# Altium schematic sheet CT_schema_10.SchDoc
size 254 x 194 mm
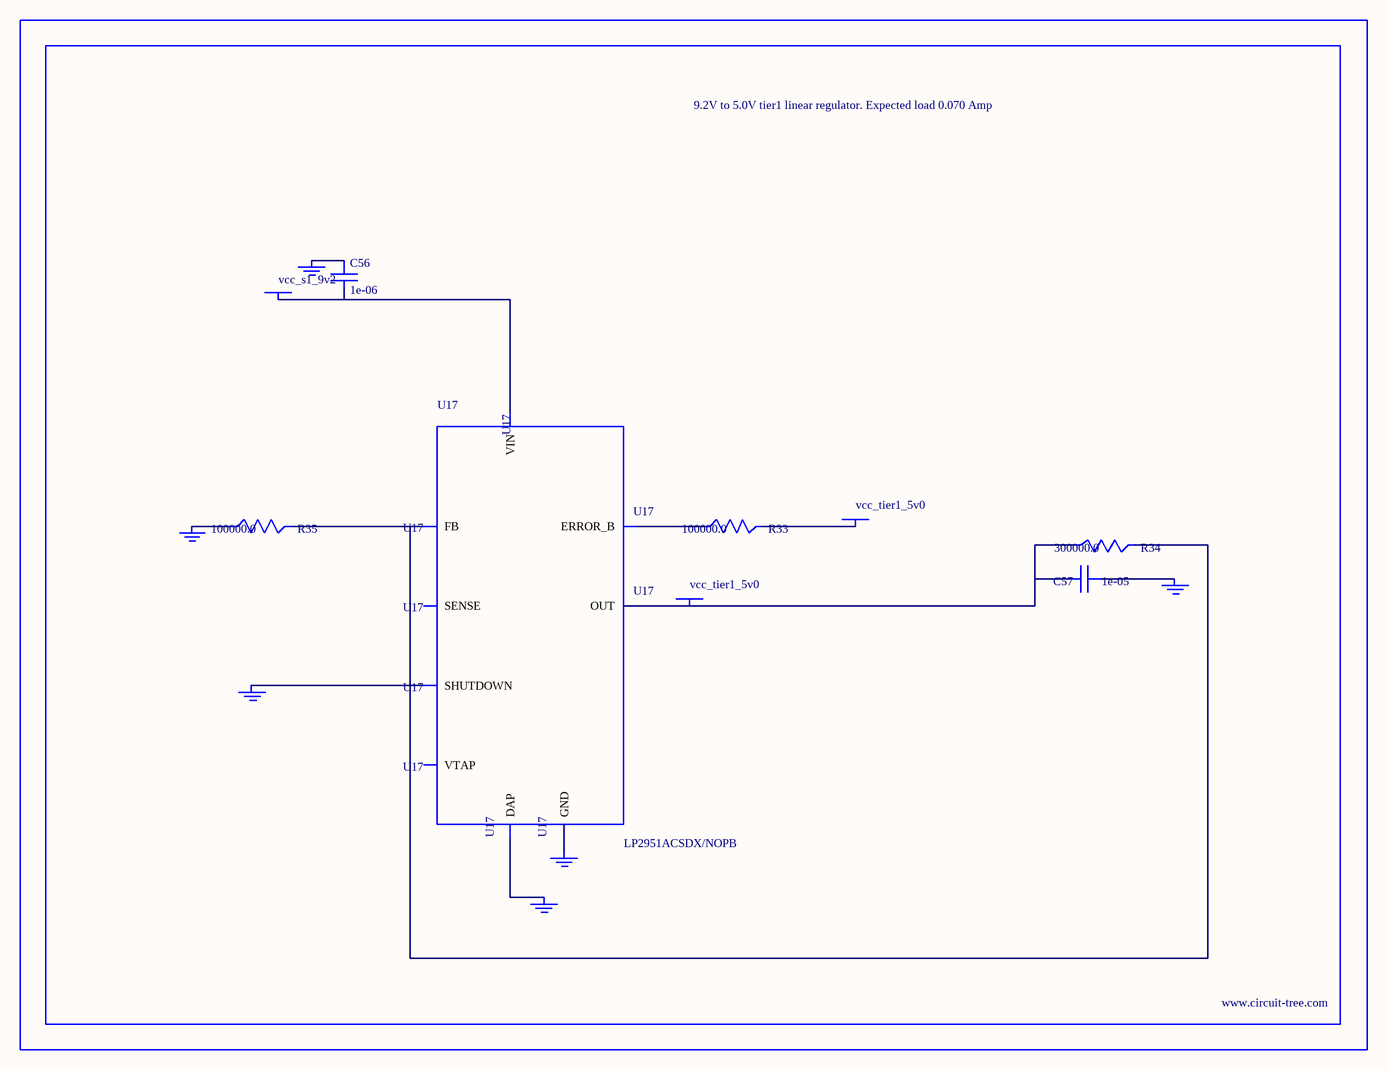
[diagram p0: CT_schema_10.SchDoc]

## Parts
BORDER9  (no value)
C56  1e-06  [C0603]
C57  1e-05  [C1210]
GND_INSTANCE_9_0  (no value)
GND_INSTANCE_9_1  (no value)
GND_INSTANCE_9_2  (no value)
GND_INSTANCE_9_3  (no value)
GND_INSTANCE_9_4  (no value)
GND_INSTANCE_9_5  (no value)
POWER_INSTANCE_9_0  vcc_tier1_5v0
POWER_INSTANCE_9_1  vcc_s1_9v2
POWER_INSTANCE_9_2  vcc_tier1_5v0
R33  100000.0  [R0603]
R34  300000.0  [R0603]
R35  100000.0  [R0603]
U17  LP2951ACSDX/NOPB  [WSON-8]

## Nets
NetC56_1: C56.1 GND_INSTANCE_9_3.0(GND)
NetC56_2: C56.2 POWER_INSTANCE_9_1.0(PWR) U17.8(VIN)
NetC57_1: C57.1 GND_INSTANCE_9_0.0(GND)
NetC57_2: C57.2 POWER_INSTANCE_9_2.0(PWR) R34.1 U17.1(OUT)
NetGND_INSTANCE_9_1_0: GND_INSTANCE_9_1.0(GND) U17.3(SHUTDOWN)
NetGND_INSTANCE_9_2_0: GND_INSTANCE_9_2.0(GND) R35.1
NetGND_INSTANCE_9_4_0: GND_INSTANCE_9_4.0(GND) U17.PAD(DAP)
NetGND_INSTANCE_9_5_0: GND_INSTANCE_9_5.0(GND) U17.4(GND)
NetPOWER_INSTANCE_9_0_0: POWER_INSTANCE_9_0.0(PWR) R33.2
NetR33_1: R33.1 U17.5(ERROR_B)
NetR34_2: R34.2 R35.2 U17.7(FB)

Not connected (* = marked no-connect by the designer): U17 2(SENSE) 6(VTAP)

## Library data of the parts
BORDER9 = BORDER_PAGE9
C56 = C0603C105K3RACTU
C57 = GRM32DR61E106MA12L
GND_INSTANCE_9_0-GND_INSTANCE_9_5 = GND
POWER_INSTANCE_9_0-POWER_INSTANCE_9_2 = PWR
R33 R35 = RC0603JR-07100KL
R34 = RC0603JR-07300KL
